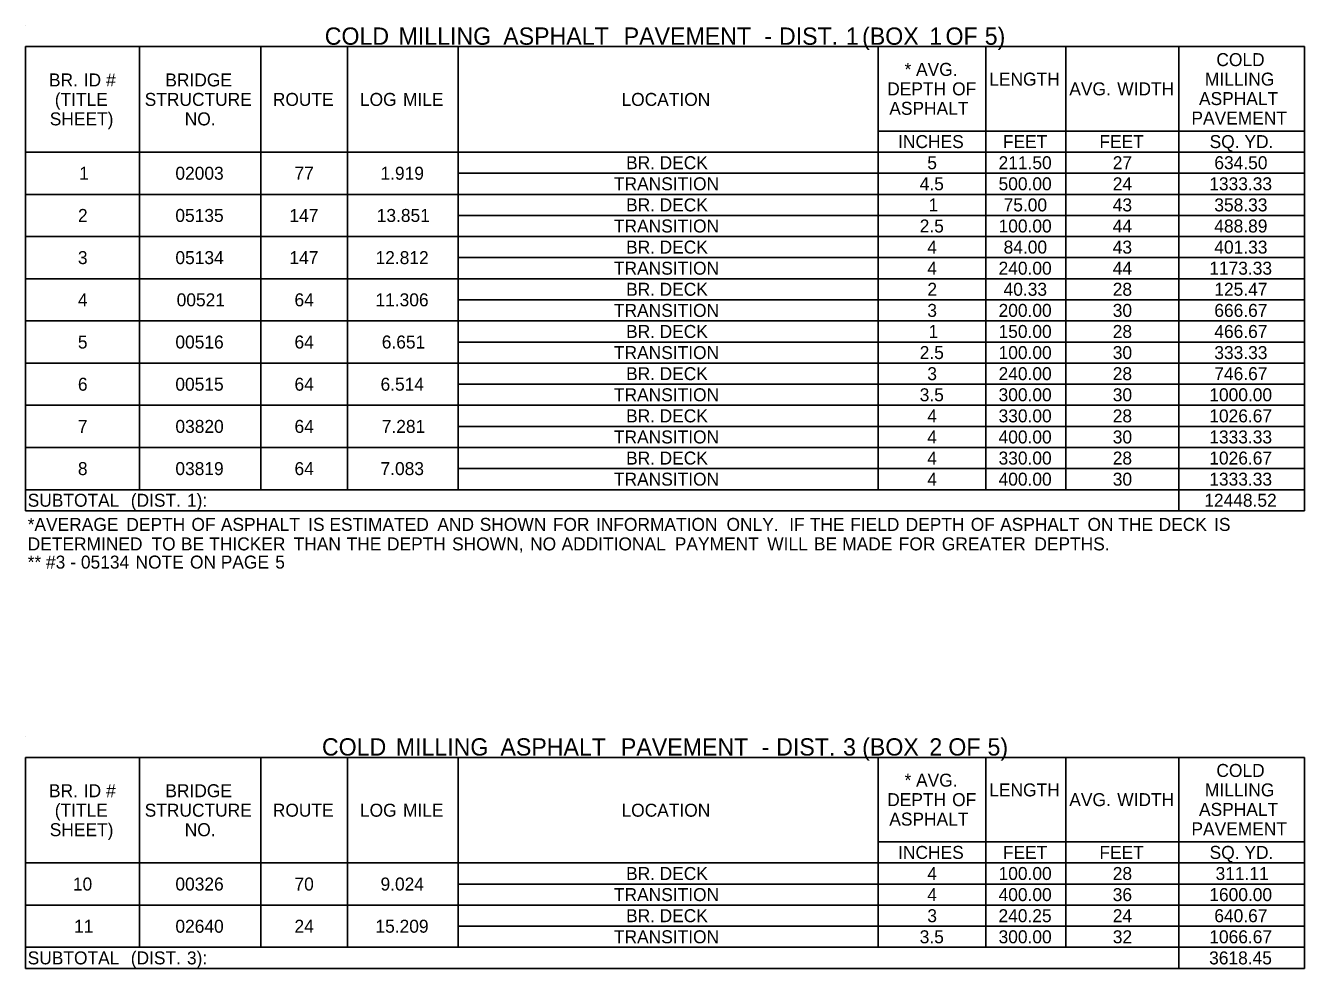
# Model space of a CAD drawing. Extents: x 544255 to 1930787, y -1947044 to 596640.
# Drawn here: x 553844 to 554435, y -1946581 to -1946145 of the extents above; entities that cross this region are included whole.
import ezdxf

# ---------------------------------------------------------------- set-up
doc = ezdxf.new("R2010")
doc.units = 0
doc.layers.add('Default', color=7, linetype='Continuous')

msp = doc.modelspace()

# ---------------------------------------------------------------- linework, layer by layer
at = {"layer": 'Default'}
for p, q in [((553844, -1946145.39), (553844, -1946145.39)), ((553844, -1946155.14), (554434.85, -1946155.14)), ((553844, -1946155.14), (554434.85, -1946155.14)), ((553844, -1946369.64), (553844, -1946155.14)), ((553896.65, -1946359.89), (553896.65, -1946155.14)), ((553952.71, -1946359.89), (553952.71, -1946155.14)), ((553992.69, -1946359.89), (553992.69, -1946155.14)), ((554043.87, -1946359.89), (554043.87, -1946155.14)), ((554237.9, -1946359.89), (554237.9, -1946155.14)), ((554287.62, -1946359.89), (554287.62, -1946155.14)), ((554324.67, -1946359.89), (554324.67, -1946155.14)), ((554376.84, -1946369.64), (554376.84, -1946155.14)), ((554434.85, -1946369.64), (554434.85, -1946155.14)), ((554237.9, -1946194.14), (554324.67, -1946194.14)), ((554237.9, -1946194.14), (554287.62, -1946194.14)), ((554287.62, -1946194.14), (554434.85, -1946194.14)), ((554324.67, -1946203.89), (554324.67, -1946194.14)), ((553844, -1946203.89), (554434.85, -1946203.89)), ((554043.87, -1946213.64), (554434.85, -1946213.64)), ((553844, -1946223.39), (554043.87, -1946223.39)), ((553844, -1946223.39), (554434.85, -1946223.39)), ((554043.87, -1946223.39), (554434.85, -1946223.39)), ((554043.87, -1946233.14), (554434.85, -1946233.14)), ((553844, -1946242.89), (554043.87, -1946242.89)), ((553844, -1946242.89), (554434.85, -1946242.89)), ((554043.87, -1946242.89), (554434.85, -1946242.89)), ((554043.87, -1946252.64), (554434.85, -1946252.64)), ((553844, -1946262.39), (554043.87, -1946262.39)), ((553844, -1946262.39), (554434.85, -1946262.39)), ((554043.87, -1946262.39), (554434.85, -1946262.39)), ((554043.87, -1946272.14), (554434.85, -1946272.14)), ((553844, -1946281.89), (554043.87, -1946281.89)), ((553844, -1946281.89), (554434.85, -1946281.89)), ((554043.87, -1946281.89), (554434.85, -1946281.89)), ((554043.87, -1946291.64), (554434.85, -1946291.64)), ((553844, -1946301.39), (554043.87, -1946301.39)), ((553844, -1946301.39), (554434.85, -1946301.39)), ((554043.87, -1946301.39), (554434.85, -1946301.39)), ((554043.87, -1946311.14), (554434.85, -1946311.14)), ((553844, -1946320.89), (554043.87, -1946320.89)), ((553844, -1946320.89), (554434.85, -1946320.89)), ((554043.87, -1946320.89), (554434.85, -1946320.89)), ((554043.87, -1946330.64), (554434.85, -1946330.64)), ((553844, -1946340.39), (554043.87, -1946340.39)), ((553844, -1946340.39), (554434.85, -1946340.39)), ((554043.87, -1946340.39), (554434.85, -1946340.39)), ((554043.87, -1946350.14), (554434.85, -1946350.14)), ((553844, -1946359.89), (554043.87, -1946359.89)), ((553844, -1946359.89), (554434.85, -1946359.89)), ((554043.87, -1946359.89), (554434.85, -1946359.89)), ((553844, -1946369.64), (554434.85, -1946369.64)), ((553844, -1946473.89), (553844, -1946473.89)), ((553844, -1946483.64), (554434.85, -1946483.64)), ((553844, -1946483.64), (554434.85, -1946483.64)), ((553844, -1946581.14), (553844, -1946483.64)), ((553896.65, -1946571.39), (553896.65, -1946483.64)), ((553952.71, -1946571.39), (553952.71, -1946483.64)), ((553992.69, -1946571.39), (553992.69, -1946483.64)), ((554043.87, -1946571.39), (554043.87, -1946483.64)), ((554237.9, -1946571.39), (554237.9, -1946483.64)), ((554287.62, -1946571.39), (554287.62, -1946483.64)), ((554324.67, -1946571.39), (554324.67, -1946483.64)), ((554376.84, -1946581.14), (554376.84, -1946483.64)), ((554434.85, -1946581.14), (554434.85, -1946483.64)), ((554237.9, -1946522.64), (554324.67, -1946522.64)), ((554237.9, -1946522.64), (554287.62, -1946522.64)), ((554287.62, -1946522.64), (554434.85, -1946522.64)), ((554324.67, -1946532.39), (554324.67, -1946522.64)), ((553844, -1946532.39), (554434.85, -1946532.39)), ((554043.87, -1946542.14), (554434.85, -1946542.14)), ((553844, -1946551.89), (554043.87, -1946551.89)), ((553844, -1946551.89), (554434.85, -1946551.89)), ((554043.87, -1946551.89), (554434.85, -1946551.89)), ((554043.87, -1946561.64), (554434.85, -1946561.64)), ((553844, -1946571.39), (554043.87, -1946571.39)), ((553844, -1946571.39), (554434.85, -1946571.39)), ((554043.87, -1946571.39), (554434.85, -1946571.39)), ((553844, -1946581.14), (554434.85, -1946581.14))]:
    msp.add_line(p, q, dxfattribs=at)

# ---------------------------------------------------------------- texts
for s, height, p in [('COLD', 8, (553982.22, -1946154.27)), (' MILLING', 8, (554013.34, -1946154.27)), (' ASPHALT', 8, (554061.71, -1946154.27)), (' PAVEMENT', 8, (554117.37, -1946154.27)), (' DIST.', 8, (554189.11, -1946154.27)), (' 1', 8, (554220.01, -1946154.27)), (' (BOX', 8, (554227.51, -1946154.27)), (' 1', 8, (554258.55, -1946154.27)), (' OF', 8, (554266.06, -1946154.27)), (' 5)', 8, (554284.17, -1946154.27)), (' -', 8, (554182.36, -1946154.27)), ('COLD', 6, (554394.17, -1946164.14)), ('*', 6, (554250.1, -1946168.64)), (' AVG.', 6, (554253.18, -1946168.64)), ('BR.', 6, (553854.8, -1946173.52)), (' ID', 6, (553868.66, -1946173.52)), (' #', 6, (553878.96, -1946173.52)), ('BRIDGE', 6, (553908.58, -1946173.52)), ('LENGTH', 6, (554289.24, -1946173.14)), ('MILLING', 6, (554388.87, -1946173.14)), ('(TITLE', 6, (553857.49, -1946182.52)), ('STRUCTURE', 6, (553899.04, -1946182.52)), ('ROUTE', 6, (553958.23, -1946182.52)), ('LOG', 6, (553998.48, -1946182.52)), (' MILE', 6, (554016.14, -1946182.52)), ('LOCATION', 6, (554119.33, -1946182.52)), ('DEPTH', 6, (554242.08, -1946177.64)), (' OF', 6, (554269.86, -1946177.64)), ('AVG.', 6, (554326.22, -1946177.64)), (' WIDTH', 6, (554346.14, -1946177.64)), ('ASPHALT', 6, (554386.13, -1946182.14)), ('ASPHALT', 6, (554243.05, -1946186.64)), ('SHEET)', 6, (553855.17, -1946191.52)), ('NO.', 6, (553917.52, -1946191.52)), ('PAVEMENT', 6, (554382.64, -1946191.14)), ('INCHES', 6, (554247.13, -1946202.02)), ('FEET', 6, (554295.52, -1946202.02)), ('FEET', 6, (554340.13, -1946202.02)), ('SQ.', 6, (554391.05, -1946202.02)), (' YD.', 6, (554404.91, -1946202.02)), ('BR.', 6, (554121.46, -1946211.77)), (' DECK', 6, (554134.71, -1946211.77)), ('5', 6, (554260.6, -1946211.77)), ('211.50', 6, (554293.54, -1946211.77)), ('27', 6, (554346.28, -1946211.77)), ('634.50', 6, (554393.23, -1946211.77)), ('1', 6, (553868.76, -1946216.64)), ('02003', 6, (553913.22, -1946216.64)), ('77', 6, (553968.23, -1946216.64)), ('1.919', 6, (554007.98, -1946216.64)), ('TRANSITION', 6, (554115.84, -1946221.52)), ('4.5', 6, (554257.1, -1946221.52)), ('500.00', 6, (554293.54, -1946221.52)), ('24', 6, (554346.3, -1946221.52)), ('1333.33', 6, (554390.89, -1946221.52)), ('2', 6, (553868.22, -1946236.14)), ('05135', 6, (553913.2, -1946236.14)), ('147', 6, (553965.9, -1946236.14)), ('13.851', 6, (554006.24, -1946236.14)), ('BR.', 6, (554121.46, -1946231.27)), (' DECK', 6, (554134.71, -1946231.27)), ('1', 6, (554261.2, -1946231.27)), ('75.00', 6, (554295.87, -1946231.27)), ('43', 6, (554346.28, -1946231.27)), ('358.33', 6, (554393.22, -1946231.27)), ('TRANSITION', 6, (554115.84, -1946241.02)), ('2.5', 6, (554257.1, -1946241.02)), ('100.00', 6, (554293.54, -1946241.02)), ('44', 6, (554346.3, -1946241.02)), ('488.89', 6, (554393.21, -1946241.02)), ('BR.', 6, (554121.46, -1946250.77)), (' DECK', 6, (554134.71, -1946250.77)), ('4', 6, (554260.63, -1946250.77)), ('84.00', 6, (554295.87, -1946250.77)), ('43', 6, (554346.28, -1946250.77)), ('401.33', 6, (554393.22, -1946250.77)), ('3', 6, (553868.18, -1946255.64)), ('05134', 6, (553913.23, -1946255.64)), ('147', 6, (553965.9, -1946255.64)), ('12.812', 6, (554005.69, -1946255.64)), ('TRANSITION', 6, (554115.84, -1946260.52)), ('4', 6, (554260.63, -1946260.52)), ('240.00', 6, (554293.54, -1946260.52)), ('44', 6, (554346.3, -1946260.52)), ('1173.33', 6, (554390.89, -1946260.52)), ('BR.', 6, (554121.46, -1946270.27)), (' DECK', 6, (554134.71, -1946270.27)), ('2', 6, (554260.65, -1946270.27)), ('40.33', 6, (554295.85, -1946270.27)), ('28', 6, (554346.28, -1946270.27)), ('125.47', 6, (554393.22, -1946270.27)), ('4', 6, (553868.2, -1946275.14)), ('00521', 6, (553913.8, -1946275.14)), ('64', 6, (553968.24, -1946275.14)), ('11.306', 6, (554005.66, -1946275.14)), ('TRANSITION', 6, (554115.84, -1946280.02)), ('3', 6, (554260.62, -1946280.02)), ('200.00', 6, (554293.54, -1946280.02)), ('30', 6, (554346.3, -1946280.02)), ('666.67', 6, (554393.22, -1946280.02)), ('5', 6, (553868.16, -1946294.64)), ('00516', 6, (553913.22, -1946294.64)), ('64', 6, (553968.24, -1946294.64)), ('6.651', 6, (554008.57, -1946294.64)), ('BR.', 6, (554121.46, -1946289.77)), (' DECK', 6, (554134.71, -1946289.77)), ('1', 6, (554261.2, -1946289.77)), ('150.00', 6, (554293.54, -1946289.77)), ('28', 6, (554346.28, -1946289.77)), ('466.67', 6, (554393.22, -1946289.77)), ('TRANSITION', 6, (554115.84, -1946299.52)), ('2.5', 6, (554257.1, -1946299.52)), ('100.00', 6, (554293.54, -1946299.52)), ('30', 6, (554346.3, -1946299.52)), ('333.33', 6, (554393.22, -1946299.52)), ('BR.', 6, (554121.46, -1946309.27)), (' DECK', 6, (554134.71, -1946309.27)), ('3', 6, (554260.62, -1946309.27)), ('240.00', 6, (554293.54, -1946309.27)), ('28', 6, (554346.28, -1946309.27)), ('746.67', 6, (554393.22, -1946309.27)), ('6', 6, (553868.18, -1946314.14)), ('00515', 6, (553913.2, -1946314.14)), ('64', 6, (553968.24, -1946314.14)), ('6.514', 6, (554008, -1946314.14)), ('TRANSITION', 6, (554115.84, -1946319.02)), ('3.5', 6, (554257.1, -1946319.02)), ('300.00', 6, (554293.54, -1946319.02)), ('30', 6, (554346.3, -1946319.02)), ('1000.00', 6, (554390.9, -1946319.02)), ('BR.', 6, (554121.46, -1946328.77)), (' DECK', 6, (554134.71, -1946328.77)), ('4', 6, (554260.63, -1946328.77)), ('330.00', 6, (554293.54, -1946328.77)), ('28', 6, (554346.28, -1946328.77)), ('1026.67', 6, (554390.89, -1946328.77)), ('7', 6, (553868.18, -1946333.64)), ('03820', 6, (553913.23, -1946333.64)), ('64', 6, (553968.24, -1946333.64)), ('7.281', 6, (554008.57, -1946333.64)), ('TRANSITION', 6, (554115.84, -1946338.52)), ('4', 6, (554260.63, -1946338.52)), ('400.00', 6, (554293.54, -1946338.52)), ('30', 6, (554346.3, -1946338.52)), ('1333.33', 6, (554390.89, -1946338.52)), ('BR.', 6, (554121.46, -1946348.27)), (' DECK', 6, (554134.71, -1946348.27)), ('4', 6, (554260.63, -1946348.27)), ('330.00', 6, (554293.54, -1946348.27)), ('28', 6, (554346.28, -1946348.27)), ('1026.67', 6, (554390.89, -1946348.27)), ('8', 6, (553868.18, -1946353.14)), ('03819', 6, (553913.21, -1946353.14)), ('64', 6, (553968.24, -1946353.14)), ('7.083', 6, (554007.99, -1946353.14)), ('TRANSITION', 6, (554115.84, -1946358.02)), ('4', 6, (554260.63, -1946358.02)), ('400.00', 6, (554293.54, -1946358.02)), ('30', 6, (554346.3, -1946358.02)), ('1333.33', 6, (554390.89, -1946358.02)), ('SUBTOTAL', 6, (553844.97, -1946367.77)), (' (DIST.', 6, (553890.37, -1946367.77)), (' 1):', 6, (553916.33, -1946367.77)), ('12448.52', 6, (554388.58, -1946367.77)), ('*AVERAGE', 6, (553844.97, -1946378.94)), (' DEPTH', 6, (553888.33, -1946378.94)), (' OF', 6, (553918.4, -1946378.94)), (' ASPHALT', 6, (553931.98, -1946378.94)), (' IS', 6, (553972.35, -1946378.94)), (' ESTIMATED', 6, (553982.16, -1946378.94)), (' AND', 6, (554032.02, -1946378.94)), (' SHOWN', 6, (554051.6, -1946378.94)), (' FOR', 6, (554085.38, -1946378.94)), (' INFORMATION', 6, (554105.29, -1946378.94)), (' ONLY.', 6, (554165.62, -1946378.94)), ('  IF', 6, (554192.37, -1946378.94)), (' THE', 6, (554204.09, -1946378.94)), (' FIELD', 6, (554222.74, -1946378.94)), (' DEPTH', 6, (554248.38, -1946378.94)), (' OF', 6, (554278.45, -1946378.94)), (' ASPHALT', 6, (554292.03, -1946378.94)), (' ON', 6, (554332.4, -1946378.94)), (' THE', 6, (554346.62, -1946378.94)), (' DECK', 6, (554365.27, -1946378.94)), (' IS', 6, (554390.87, -1946378.94)), ('DETERMINED', 6, (553844.97, -1946387.94)), (' TO', 6, (553899.96, -1946387.94)), (' BE', 6, (553913.55, -1946387.94)), (' THICKER', 6, (553926.62, -1946387.94)), (' THAN', 6, (553965.63, -1946387.94)), (' THE', 6, (553990.1, -1946387.94)), (' DEPTH', 6, (554008.75, -1946387.94)), (' SHOWN,', 6, (554038.82, -1946387.94)), (' NO', 6, (554074.86, -1946387.94)), (' ADDITIONAL', 6, (554089.39, -1946387.94)), (' PAYMENT', 6, (554141.73, -1946387.94)), (' WILL', 6, (554184.42, -1946387.94)), (' BE', 6, (554206.01, -1946387.94)), (' MADE', 6, (554219.08, -1946387.94)), (' FOR', 6, (554245.18, -1946387.94)), (' GREATER', 6, (554265.09, -1946387.94)), (' DEPTHS.', 6, (554307.84, -1946387.94)), ('**', 6, (553844.97, -1946396.34)), (' #3', 6, (553851.2, -1946396.34)), (' -', 6, (553862.47, -1946396.34)), (' 05134', 6, (553867.33, -1946396.34)), (' NOTE', 6, (553892.55, -1946396.34)), (' ON', 6, (553917.72, -1946396.34)), (' PAGE', 6, (553931.94, -1946396.34)), (' 5', 6, (553957.12, -1946396.34)), ('COLD', 8, (553980.93, -1946482.77)), (' MILLING', 8, (554012.05, -1946482.77)), (' ASPHALT', 8, (554060.42, -1946482.77)), (' PAVEMENT', 8, (554116.08, -1946482.77)), (' DIST.', 8, (554187.82, -1946482.77)), (' 3', 8, (554218.72, -1946482.77)), (' (BOX', 8, (554227.55, -1946482.77)), (' 2', 8, (554258.59, -1946482.77)), (' OF', 8, (554267.35, -1946482.77)), (' 5)', 8, (554285.46, -1946482.77)), (' -', 8, (554181.07, -1946482.77)), ('COLD', 6, (554394.17, -1946492.64)), ('BR.', 6, (553854.8, -1946502.02)), (' ID', 6, (553868.66, -1946502.02)), (' #', 6, (553878.96, -1946502.02)), ('BRIDGE', 6, (553908.58, -1946502.02)), ('*', 6, (554250.1, -1946497.14)), (' AVG.', 6, (554253.18, -1946497.14)), ('LENGTH', 6, (554289.24, -1946501.64)), ('MILLING', 6, (554388.87, -1946501.64)), ('DEPTH', 6, (554242.08, -1946506.14)), (' OF', 6, (554269.86, -1946506.14)), ('AVG.', 6, (554326.22, -1946506.14)), (' WIDTH', 6, (554346.14, -1946506.14)), ('(TITLE', 6, (553857.49, -1946511.02)), ('STRUCTURE', 6, (553899.04, -1946511.02)), ('ROUTE', 6, (553958.23, -1946511.02)), ('LOG', 6, (553998.48, -1946511.02)), (' MILE', 6, (554016.14, -1946511.02)), ('LOCATION', 6, (554119.33, -1946511.02)), ('ASPHALT', 6, (554386.13, -1946510.64)), ('SHEET)', 6, (553855.17, -1946520.02)), ('NO.', 6, (553917.52, -1946520.02)), ('ASPHALT', 6, (554243.05, -1946515.14)), ('PAVEMENT', 6, (554382.64, -1946519.64)), ('INCHES', 6, (554247.13, -1946530.52)), ('FEET', 6, (554295.52, -1946530.52)), ('FEET', 6, (554340.13, -1946530.52)), ('SQ.', 6, (554391.05, -1946530.52)), (' YD.', 6, (554404.91, -1946530.52)), ('BR.', 6, (554121.46, -1946540.27)), (' DECK', 6, (554134.71, -1946540.27)), ('4', 6, (554260.63, -1946540.27)), ('100.00', 6, (554293.54, -1946540.27)), ('28', 6, (554346.28, -1946540.27)), ('311.11', 6, (554393.8, -1946540.27)), ('10', 6, (553865.86, -1946545.14)), ('00326', 6, (553913.22, -1946545.14)), ('70', 6, (553968.24, -1946545.14)), ('9.024', 6, (554008, -1946545.14)), ('TRANSITION', 6, (554115.84, -1946550.02)), ('4', 6, (554260.63, -1946550.02)), ('400.00', 6, (554293.54, -1946550.02)), ('36', 6, (554346.28, -1946550.02)), ('1600.00', 6, (554390.9, -1946550.02)), ('BR.', 6, (554121.46, -1946559.77)), (' DECK', 6, (554134.71, -1946559.77)), ('3', 6, (554260.62, -1946559.77)), ('240.25', 6, (554293.5, -1946559.77)), ('24', 6, (554346.3, -1946559.77)), ('640.67', 6, (554393.22, -1946559.77)), ('11', 6, (553866.43, -1946564.64)), ('02640', 6, (553913.23, -1946564.64)), ('24', 6, (553968.24, -1946564.64)), ('15.209', 6, (554005.65, -1946564.64)), ('TRANSITION', 6, (554115.84, -1946569.52)), ('3.5', 6, (554257.1, -1946569.52)), ('300.00', 6, (554293.54, -1946569.52)), ('32', 6, (554346.32, -1946569.52)), ('1066.67', 6, (554390.89, -1946569.52)), (' (DIST.', 6, (553890.37, -1946579.27)), (' 3):', 6, (553916.33, -1946579.27)), ('SUBTOTAL', 6, (553844.97, -1946579.27)), ('3618.45', 6, (554390.82, -1946579.27))]:
    msp.add_text(s, height=height, dxfattribs=at).set_placement(p)

doc.saveas('drawing.dxf')
